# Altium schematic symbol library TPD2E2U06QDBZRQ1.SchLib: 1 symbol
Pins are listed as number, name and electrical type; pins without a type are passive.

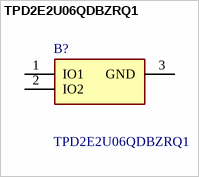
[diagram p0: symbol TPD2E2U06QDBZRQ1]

## TPD2E2U06QDBZRQ1
designator B?
Automotive Dual-Channel High-Speed ESD Protection Device; Manufacturer_Name: Texas Instruments; Geometry.Height: 0.95mm
footprint SOT95P237X95-3N
pins: 1 IO1, 2 IO2, 3 GND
